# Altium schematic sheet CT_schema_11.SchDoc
size 274 x 160 mm
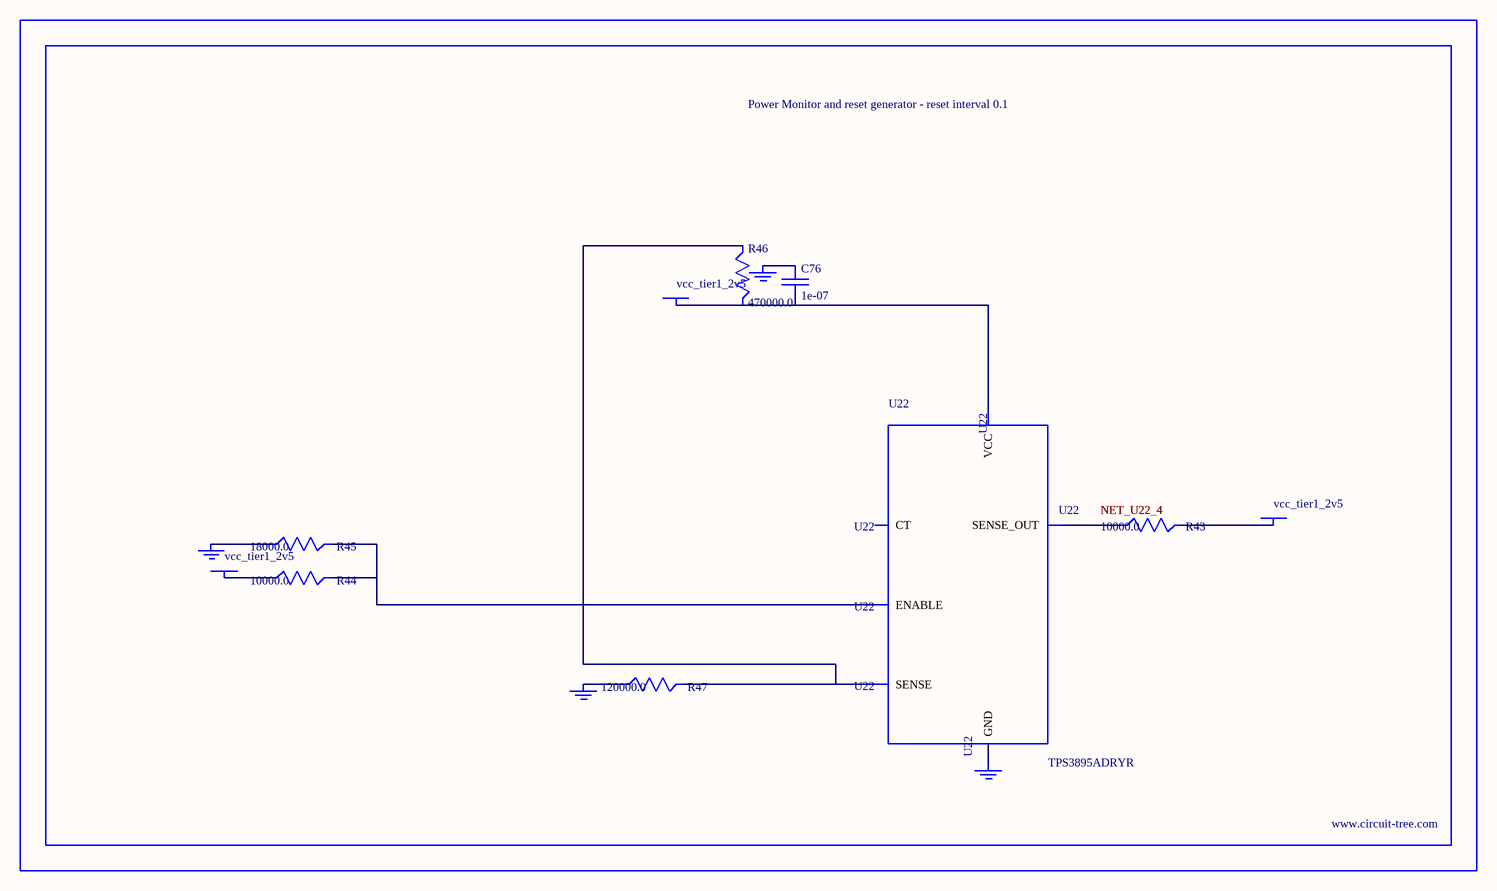
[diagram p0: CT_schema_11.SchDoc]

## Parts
BORDER10  (no value)
C76  1e-07  [C0402]
GND_INSTANCE_10_0  (no value)
GND_INSTANCE_10_1  (no value)
GND_INSTANCE_10_2  (no value)
GND_INSTANCE_10_3  (no value)
POWER_INSTANCE_10_0  vcc_tier1_2v5
POWER_INSTANCE_10_1  vcc_tier1_2v5
POWER_INSTANCE_10_2  vcc_tier1_2v5
R43  10000.0  [R0603]
R44  10000.0  [R0603]
R45  18000.0  [R0603]
R46  470000.0  [R0603]
R47  120000.0  [R0603]
U22  TPS3895ADRYR  [SON-6]

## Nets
NetC76_1: C76.1 GND_INSTANCE_10_2.0(GND)
NetC76_2: C76.2 POWER_INSTANCE_10_2.0(PWR) R46.2 U22.6(VCC)
NetGND_INSTANCE_10_0_0: GND_INSTANCE_10_0.0(GND) R45.1
NetGND_INSTANCE_10_1_0: GND_INSTANCE_10_1.0(GND) R47.1
NetGND_INSTANCE_10_3_0: GND_INSTANCE_10_3.0(GND) U22.2(GND)
NetPOWER_INSTANCE_10_0_0: POWER_INSTANCE_10_0.0(PWR) R44.1
NetPOWER_INSTANCE_10_1_0: POWER_INSTANCE_10_1.0(PWR) R43.2
NetR43_1: R43.1 U22.4(SENSE_OUT)
NetR44_2: R44.2 R45.2 U22.1(ENABLE)
NetR46_1: R46.1 R47.2 U22.3(SENSE)

Not connected (* = marked no-connect by the designer): U22 5(CT)

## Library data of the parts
BORDER10 = BORDER_PAGE10
C76 = C0402C104K3RACTU
GND_INSTANCE_10_0-GND_INSTANCE_10_3 = GND
POWER_INSTANCE_10_0-POWER_INSTANCE_10_2 = PWR
R43 R44 = RC0603JR-0710KL
R45 = RC0603JR-0718KL
R46 = RC0603JR-07470KL
R47 = RC0603JR-07120KL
